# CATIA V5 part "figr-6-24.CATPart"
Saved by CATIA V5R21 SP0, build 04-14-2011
Part number: Part1
Bounding box of the stored display mesh (mm): x -70 to 0, y 0 to 90, z -45 to 145
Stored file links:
  D:\CATIAV5R21-WORK\c06_cat_v5r21\catia-files\c05-d30.CATPart
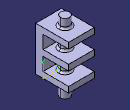
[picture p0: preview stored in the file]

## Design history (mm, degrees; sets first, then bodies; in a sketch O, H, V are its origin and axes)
Body1 (main body)
  Sketch1 on zx-plane, origin (0, 0, 0), H (-1, 0, 0), V (0, 0, 1)
    line L1 (0, 0) -> (70, 0)
    line L2 (70, 0) -> (70, 120)
    line L3 (70, 120) -> (0, 120)
    line L4 (0, 120) -> (0, 0)
    length L3 = 70
    length L2 = 120
    horizontal: L1 H, L3 H
    vertical: L2 V, L4 V
  Pad1: profile Sketch1, direction (0, 1, 0), length 20
  Sketch2 on end face of Pad1, origin (0, 20, 0), H (-1, 0, 0), V (0, 0, 1)
    projected line E1 (70, 120) -> (0, 120) from edge [face of Pad1 from Sketch1.L3 | end face of Pad1]
    point P1 (70, 120)
    line L1 (70, 120) -> (70, 104)
    line L2 (70, 104) -> (0, 104)
    line L3 (0, 104) -> (0, 120)
    point P3 (70, 120)
    length L1 = 16
    horizontal: L2 H
    vertical: L1 V, L3 V
    coincidence: P1 P3
  Sketch3 on end face of Pad1, origin (0, 20, 0), H (-1, 0, 0), V (0, 0, 1)
  Pad2: profile Sketch2, direction (0, 1, 0), length 70
  Sketch4 on end face of Pad1, origin (0, 20, 0), H (-1, 0, 0), V (0, 0, 1)
    projected line E1 (0, 0) -> (70, 0) from edge [face of Pad1 from Sketch1.L1 | end face of Pad1]
    point P1 (0, 0)
    point P3 (0, 16)
    line L1 (0, 16) -> (70, 16)
    line L2 (70, 16) -> (70, 0)
    line L3 (0, 0) -> (0, 16)
    point P5 (0, 0)
    length L2 = 16
    coincidence: P3 V, P1 P5
    horizontal: L1 H
    vertical: L2 V, L3 V
  Pad3: profile Sketch4, direction (0, 1, 0), length 70
  Sketch5 on end face of Pad1, origin (0, 20, 0), H (-1, 0, 0), V (0, 0, 1)
    point P1 (0, 68)
    line L1 (0, 68) -> (70, 68)
    line L2 (70, 68) -> (70, 52)
    line L3 (70, 52) -> (0, 52)
    line L4 (0, 52) -> (0, 68)
    coincidence: P1 V
    horizontal: L1 H, L3 H
    vertical: L2 V, L4 V
  Pad4: profile Sketch5, direction (0, 1, 0), length 70
  Sketch6 on face of Pad2, origin (0, 0, 120), H (1, 0, 0), V (0, 1, 0)
    circle A1 centre (-35, 45) radius 12.5
    radius A1 = 12.5
  Pad5: profile Sketch6, direction (0, 0, 1), length 25, opposite side length 165
  Fillet1: radius 5, on 1 edge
